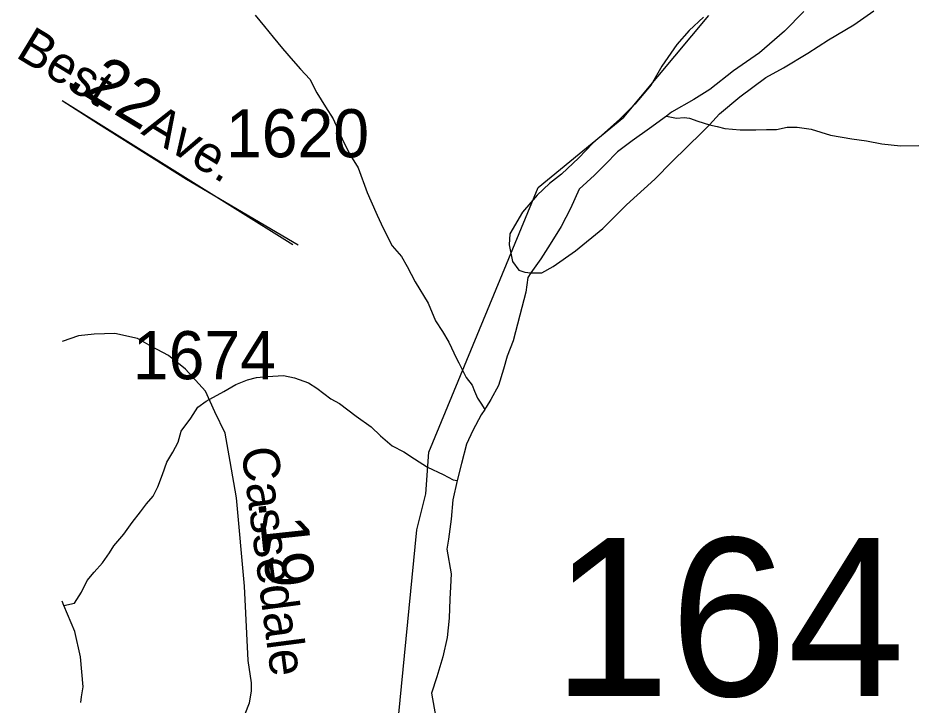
# Model space of a CAD drawing. Extents: x 2315291 to 2336543, y 597177 to 615230.
# Drawn here: x 2315630 to 2317961, y 604731 to 606517 of the extents above; entities that cross this region are included whole.
import ezdxf

# ---------------------------------------------------------------- set-up
doc = ezdxf.new("R2010")
doc.units = 0
for name, color, linetype in [('Exist Hydrographic Creek Single Shore', 7, 'Continuous'), ('Exist Hydrographic Misc Water Feature', 7, 'Continuous'), ('Exist Road Non-System Type 51', 7, 'Continuous'), ('Exist Road Secondary Mileage Hundredths English Label', 7, 'Continuous'), ('Exist Road Secondary Structure Standard Bridge Number Label', 7, 'Continuous'), ('Exist Road Secondary Type 51 Attributed', 7, 'Continuous'), ('Exist Road Secondary Type 51 Label', 7, 'Continuous'), ('Exist Road Secondary Type 51 Number Label', 7, 'Continuous')]:
    doc.layers.add(name, color=color, linetype=linetype)

msp = doc.modelspace()

# ---------------------------------------------------------------- linework, layer by layer
at = {"layer": 'Exist Hydrographic Creek Single Shore'}
msp.add_lwpolyline([(2315744.5, 602054.5), (2315989.3, 602291.1), (2316112.3, 602456.9), (2316218.3, 602658.1), (2316316.3, 602868.8), (2316445.3, 603235), (2316500.2, 603588.3), (2316583.3, 604336.6), (2316666.1, 605186.6), (2316690.1, 605279.5), (2316697.3, 605388), (2316981.3, 606075.5), (2317204.2, 606258.5), (2317425.2, 606522.7)], dxfattribs=at)
at = {"layer": 'Exist Hydrographic Misc Water Feature'}
for points in [[(2316246, 606523.8), (2316270.4, 606494.2), (2316292.7, 606466.5), (2316317.1, 606436.9), (2316345.2, 606405), (2316363.9, 606383.2), (2316388.1, 606357.7), (2316406.3, 606321.6), (2316428.7, 606285.8), (2316449, 606254.4), (2316475.6, 606194.4), (2316493.9, 606158.8), (2316514.2, 606127), (2316537, 606063.1), (2316547, 606041.3), (2316563.2, 606003.6), (2316573.7, 605981.8), (2316586, 605956), (2316602.4, 605923.9), (2316626.6, 605896.4), (2316641.1, 605870.6), (2316661.6, 605830.6), (2316695.7, 605775.2), (2316714.5, 605729.4), (2316732.8, 605701.5), (2316749, 605673.9), (2316769.7, 605631.9), (2316775.2, 605620.1), (2316794.1, 605582.4), (2316810.3, 605562.5), (2316816.2, 605546.6), (2316824.2, 605528.7), (2316832.6, 605515), (2316842.7, 605498.8)], [(2317411.3, 606518.3), (2317373.8, 606484.2), (2317342.2, 606447.6), (2317303.2, 606391.5), (2317275.5, 606342.9), (2317232.3, 606292.6), (2317192.5, 606252.4), (2317123.2, 606191.4), (2317087.5, 606153), (2317042.2, 606110.7), (2317010.6, 606086.3), (2316978.6, 606055.8), (2316941.1, 606011.6), (2316908.1, 605955.4), (2316906.3, 605927.2), (2316914.7, 605883.4), (2316931.1, 605861.4), (2316947.1, 605855.8), (2316962.8, 605853.8)], [(2317671.3, 606533.1), (2317621.7, 606482.6), (2317556.7, 606425.9), (2317489, 606379.3), (2317427.3, 606330.6), (2317386.1, 606304.4), (2317328.2, 606271.7), (2317314.7, 606261.6)], [(2317426.5, 606238.6), (2317452.5, 606267.2), (2317505.8, 606311.5), (2317573.3, 606362.1), (2317619, 606386.5), (2317682.4, 606425.2), (2317735.7, 606460.1), (2317801.7, 606498.5), (2317853.2, 606534.9)], [(2317314.7, 606261.6), (2317270.6, 606228.8), (2317225.3, 606196.8), (2317187.4, 606168.4), (2317155.6, 606135.9), (2317127.9, 606107.6), (2317088.3, 606071.4), (2317065.2, 606020.9), (2317041.6, 605974.6), (2317012.3, 605928.3), (2316988.5, 605890.1), (2316962.8, 605853.8)], [(2317314.7, 606261.6), (2317340.6, 606255.7), (2317360.4, 606257.9), (2317374.6, 606256.2), (2317396.7, 606248.4), (2317426.5, 606238.6)], [(2316962.8, 605853.8), (2316990.9, 605854.1), (2317020.5, 605870.7), (2317078.3, 605911.1), (2317149.6, 605969.7), (2317210.8, 606030.6), (2317284.4, 606097.4), (2317329.5, 606143.7), (2317407, 606218.5), (2317426.5, 606238.6)], [(2317426.5, 606238.6), (2317446.6, 606234.8), (2317466.5, 606229), (2317506.6, 606225.4), (2317546.8, 606225.8), (2317574.9, 606226.4), (2317600.8, 606226.6), (2317628.2, 606233), (2317654.7, 606233.1), (2317690.8, 606227.7), (2317740.8, 606212), (2317796.6, 606202.8), (2317834.7, 606197.1), (2317874.7, 606189.4), (2317922.7, 606184.2), (2317970.9, 606184.7)], [(2316962.8, 605853.8), (2316955.1, 605842), (2316949.5, 605803.9), (2316933.9, 605743.8), (2316916.9, 605677.4), (2316900.9, 605637.3), (2316891.5, 605603.4), (2316878.2, 605561.2), (2316858.5, 605524.9), (2316846.6, 605504.7), (2316842.7, 605498.8)], [(2315748.9, 604989.5), (2315776.8, 604995.8), (2315794.7, 605024), (2315810.2, 605054.1), (2315827.9, 605076.1), (2315849.4, 605100.4), (2315867.5, 605126.5), (2315879.3, 605144.6), (2315904.8, 605174.9), (2315926.3, 605205.3), (2315948, 605233.2), (2315964.2, 605253.5), (2315981.5, 605273.6), (2315993.2, 605297.8), (2316005.5, 605330.1), (2316016.5, 605362), (2316032.5, 605388), (2316046.3, 605414.3), (2316054.3, 605442.3), (2316079.5, 605476.6), (2316096.9, 605504.8), (2316118.6, 605521), (2316165, 605545.7), (2316196.4, 605563.7), (2316226.1, 605576.2), (2316250.1, 605582.4), (2316278.2, 605584.6), (2316320.2, 605587.2), (2316348.1, 605581.4), (2316384.6, 605567.8), (2316406.3, 605554), (2316442.6, 605526.6), (2316465, 605514.8), (2316509.1, 605481.3), (2316547.4, 605453.6), (2316572, 605430.1), (2316602.2, 605404.4), (2316632.3, 605388.6), (2316660.4, 605371), (2316694.4, 605349.2), (2316734.6, 605329.7), (2316760.9, 605316.1), (2316770.7, 605314.2)], [(2316842.7, 605498.8), (2316833, 605484.9), (2316811.5, 605444.7), (2316795.7, 605408.5), (2316782.2, 605358.3), (2316770.7, 605314.2)], [(2316770.7, 605314.2), (2316759.4, 605264), (2316755.7, 605214.2), (2316748.4, 605162.2), (2316744.5, 605136.1), (2316755.5, 605071.9), (2316753.7, 605038.2), (2316752.1, 605005.9), (2316750.6, 604956.3), (2316745.3, 604906), (2316734, 604855.8), (2316718.4, 604803.8), (2316704.7, 604761.6), (2316719.9, 604673.8), (2316726.4, 604598.2), (2316729.5, 604540.1), (2316730.1, 604462.2), (2316738.5, 604428.5), (2316722.9, 604367.9), (2316715.6, 604336.2)], [(2315748.9, 604989.5), (2315744.5, 605000.8)], [(2315793.4, 604737.8), (2315795.3, 604752.1), (2315799.2, 604777.9), (2315792.2, 604856), (2315777.6, 604921.9), (2315748.9, 604989.5)]]:
    msp.add_lwpolyline(points, dxfattribs=at)
at = {"layer": 'Exist Road Non-System Type 51'}
for points in [[(2316358.1, 605925.8), (2316067.5, 606096.4), (2315839.5, 606240.9), (2315744.5, 606300.7)], [(2316141.1, 605492.6), (2316117.2, 605547), (2316065.6, 605604.1), (2316021.4, 605639.1), (2315977.2, 605663), (2315940.4, 605683.3), (2315881.5, 605696.2), (2315828.1, 605694.4), (2315787.6, 605690.7), (2315744.5, 605675.8)]]:
    msp.add_lwpolyline(points, dxfattribs=at)
at = {"layer": 'Exist Road Secondary Type 51 Attributed'}
for points in [[(2315744.5, 606302), (2316343.8, 605927.6)], [(2316124.3, 604463.3), (2316161.3, 604557.8), (2316231.3, 604736.5), (2316237.1, 604766.5), (2316236.8, 604788.5), (2316228, 604846.4), (2316218.4, 605039.4), (2316198.2, 605269.7), (2316181.6, 605363.6), (2316168.7, 605437.3), (2316141.1, 605492.6)]]:
    msp.add_lwpolyline(points, dxfattribs=at)

# ---------------------------------------------------------------- texts
at = {"layer": 'Exist Road Secondary Mileage Hundredths English Label'}
for s, rotation, p in [('.22', 328.751, (2315755.6, 606342.2)), ('.19', 276.1193, (2316253.3, 605261.4))]:
    msp.add_text(s, height=125, rotation=rotation, dxfattribs=at).set_placement(p)
at = {"layer": 'Exist Road Secondary Structure Standard Bridge Number Label'}
msp.add_text('164', height=410.1, dxfattribs=at).set_placement((2317019.1, 604754.5))
at = {"layer": 'Exist Road Secondary Type 51 Label'}
for s, rotation, p in [('Best', 328.751, (2315621.1, 606416.3)), ('Ave.', 328.751, (2315947.2, 606216.8)), ('Cassedale', 277.4638, (2316209.9, 605396.7))]:
    msp.add_text(s, height=95, rotation=rotation, dxfattribs=at).set_placement(p)
at = {"layer": 'Exist Road Secondary Type 51 Number Label'}
for s, p in [('1620', (2316170.4, 606154.4)), ('1674', (2315928.5, 605577.6))]:
    msp.add_text(s, height=125, dxfattribs=at).set_placement(p)

doc.saveas('drawing.dxf')
